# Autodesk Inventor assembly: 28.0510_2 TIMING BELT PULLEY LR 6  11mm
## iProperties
Created: 2007-06
Part Number: 28.0510_2 TIMING BELT PULLEY LR 6  11mm
Document SubType Name: Assembly
Designer: Andy Moles
Author: Andy Moles
